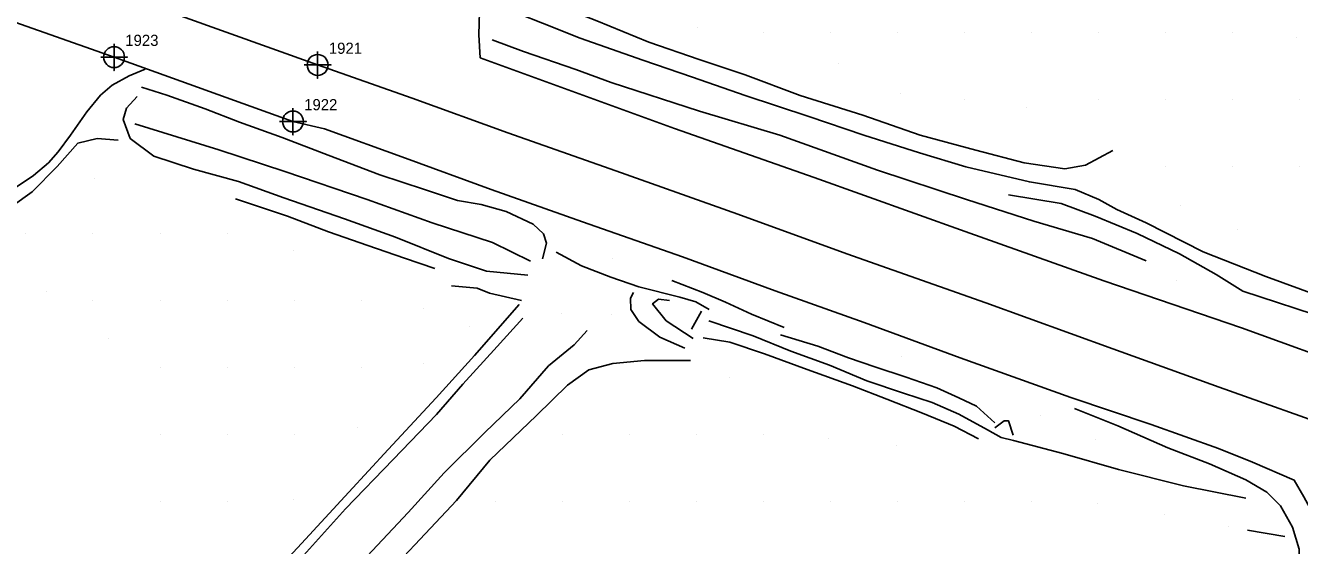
# Model space of a CAD drawing. Extents: x 1497074 to 1501343, y 481943 to 486114.
# Drawn here: x 1500304.3 to 1500589.4, y 482477.4 to 482593.8 of the extents above; entities that cross this region are included whole.
import ezdxf

# ---------------------------------------------------------------- set-up
doc = ezdxf.new("R2010")
doc.units = 0
for name, color, linetype in [('Exist DTM Crownline', 7, 'Continuous'), ('Exist DTM Crownline Cogo Number', 7, 'Continuous'), ('Exist DTM Crownline Cogo Point CELL', 7, 'Continuous'), ('Exist Roads EOP', 7, 'Continuous'), ('Exist Roads EOP Cogo Number', 7, 'Continuous'), ('Exist Roads EOP Cogo Point CELL', 7, 'Continuous'), ('PH Exist DTM Breakline', 7, 'Continuous'), ('PH Exist DTM Point', 7, 'Continuous')]:
    doc.layers.add(name, color=color, linetype=linetype)

msp = doc.modelspace()

# ---------------------------------------------------------------- linework, layer by layer
at = {"layer": 'Exist DTM Crownline'}
msp.add_lwpolyline([(1499395.36, 482985.02), (1499443.87, 482960.81), (1499493.08, 482936.36), (1499540.5, 482912.88), (1499586.46, 482890.36), (1499633.9, 482867.41), (1499680.88, 482845.25), (1499726.12, 482824.18), (1499773.19, 482803.77), (1499819.04, 482785.34), (1499906.6, 482751.56), (1499930.69, 482742.84), (1499979.87, 482724.77), (1500026.26, 482708.17), (1500077.15, 482689.67), (1500127.52, 482671.55), (1500177.68, 482653.78), (1500231.5, 482634.52), (1500279.65, 482617.19), (1500328.73, 482599.71), (1500369.66, 482584.94)], dxfattribs=at)
at = {"layer": 'Exist DTM Crownline Cogo Point CELL'}
msp.add_lwpolyline([(1500369.66, 482587.94), (1500369.66, 482581.94), (1500369.66, 482584.94), (1500372.66, 482584.94), (1500366.66, 482584.94)], dxfattribs=at)
msp.add_circle((1500369.66, 482584.94), 2.34, dxfattribs=at)
at = {"layer": 'Exist Roads EOP'}
msp.add_lwpolyline([(1500364.14, 482572.3), (1500324.1, 482586.7), (1500274.47, 482604.24), (1500226.4, 482621.51), (1500172.89, 482640.65), (1500123.05, 482658.39), (1500072.51, 482676.64), (1500021.62, 482694.94), (1499975.28, 482711.55), (1499955.26, 482716.33), (1499949.38, 482714.38), (1499941.38, 482710.37), (1499928.12, 482699.94), (1499921.66, 482694.39), (1499904.23, 482677.62), (1499903.33, 482678.08), (1499900.77, 482675.86), (1499864.51, 482643.53), (1499854.11, 482635.15), (1499853.12, 482633.84), (1499832.56, 482616.27)], dxfattribs=at)
at = {"layer": 'Exist Roads EOP Cogo Point CELL'}
for points in [[(1500324.1, 482589.7), (1500324.1, 482583.7), (1500324.1, 482586.7), (1500327.1, 482586.7), (1500321.1, 482586.7)], [(1500364.14, 482575.3), (1500364.14, 482569.3), (1500364.14, 482572.3), (1500367.14, 482572.3), (1500361.14, 482572.3)]]:
    msp.add_lwpolyline(points, dxfattribs=at)
for centre in [(1500324.1, 482586.7), (1500364.14, 482572.3)]:
    msp.add_circle(centre, 2.34, dxfattribs=at)
at = {"layer": 'PH Exist DTM Breakline'}
for points in [[(1500547.62, 482565.77), (1500541.54, 482562.52), (1500536.9, 482561.72), (1500527.81, 482563.03), (1500516.97, 482565.85), (1500504.53, 482569.25), (1500491.66, 482573.73), (1500477.65, 482578.13), (1500465.31, 482582.73), (1500455.04, 482586.17), (1500443.76, 482590.06), (1500432.14, 482594.82), (1500421.54, 482598.92), (1500418.01, 482600.86), (1500417.69, 482602.83), (1500418.26, 482607.14), (1500421.14, 482612.28)], [(1500405.93, 482599.51), (1500405.73, 482591.71), (1500406.05, 482586.53)], [(1500597.39, 482531.89), (1500581.86, 482537.56), (1500567.86, 482543.08), (1500555.09, 482549.62), (1500548.51, 482552.62), (1500544.53, 482554.85), (1500539.24, 482557.03), (1500528.98, 482558.76), (1500514.76, 482562.16), (1500504.39, 482565.28), (1500491.91, 482569.24), (1500479.6, 482573.43), (1500465.31, 482578.1), (1500453.59, 482582.18), (1500442.47, 482586), (1500428.38, 482590.96), (1500419.95, 482594.33), (1500414.71, 482596.39), (1500410.57, 482596.92)], [(1500408.71, 482590.6), (1500415.76, 482587.94), (1500427.44, 482583.92), (1500435.32, 482580.99), (1500455.09, 482574.64), (1500473.11, 482569.22), (1500494.93, 482561.37), (1500514.86, 482554.8), (1500529.97, 482549.97), (1500543.06, 482546.06), (1500555.08, 482541.13)], [(1500406.05, 482586.53), (1500449.56, 482570.71), (1500480.79, 482559.72), (1500514.61, 482547.63), (1500545.65, 482536.59), (1500576.45, 482526.09), (1500603.2, 482516.43), (1500637.04, 482504.51), (1500670.84, 482492.41), (1500696.34, 482483.22)], [(1500331.04, 482584.04), (1500327.45, 482582.49), (1500323.67, 482580.42), (1500321.08, 482578.16), (1500317.97, 482574.44), (1500314.37, 482569.2), (1500311.58, 482565.5), (1500309.42, 482563.01), (1500306.06, 482560.22), (1500301.06, 482556.84)], [(1500369.66, 482584.94), (1500390.85, 482577.55), (1500412.23, 482569.72), (1500436.39, 482561.28), (1500463.73, 482551.56), (1500488.07, 482542.65), (1500519.2, 482531.68), (1500547.67, 482521.38), (1500571.4, 482512.81), (1500599.53, 482502.81), (1500623.37, 482494.22), (1500646.19, 482486.12), (1500679.44, 482473.93), (1500690.61, 482470.06)], [(1500416.68, 482537.86), (1500407.48, 482538.76), (1500398.98, 482541.63), (1500387.05, 482546.43), (1500375.66, 482550.5), (1500362.06, 482555.21), (1500351.97, 482558.88), (1500341.9, 482561.63), (1500333, 482564.53), (1500327.73, 482568.49), (1500326.14, 482572.74), (1500326.9, 482575.27), (1500329.27, 482577.92)], [(1500419.97, 482541.55), (1500420.88, 482545.08), (1500420.24, 482547.17), (1500417.93, 482549.28), (1500411.85, 482552.16), (1500406.26, 482553.73), (1500400.97, 482554.57), (1500393.58, 482557.04), (1500383.58, 482560.33), (1500371.98, 482564.73), (1500361.75, 482568.72), (1500352.2, 482572.12), (1500344.45, 482575.09), (1500335.89, 482578.2), (1500330.24, 482579.97)], [(1500595.23, 482475.62), (1500594.21, 482480.19), (1500592.65, 482484.14), (1500590.39, 482488.29), (1500588.26, 482492.01), (1500578.87, 482496.04), (1500571.31, 482499.06), (1500556.23, 482504.45), (1500538.22, 482510.5), (1500513.46, 482519.4), (1500491.97, 482527.27), (1500472.06, 482534.37), (1500451.31, 482541.98), (1500428.93, 482549.82), (1500408.49, 482557.07), (1500389.35, 482564.11), (1500371.23, 482570.64), (1500364.14, 482572.3)], [(1500328.74, 482571.74), (1500347.55, 482565.97), (1500362.35, 482561.08), (1500380.71, 482554.84), (1500395.32, 482549.61), (1500408.78, 482545.19), (1500417.33, 482541.02)], [(1500316.01, 482567.47), (1500311.38, 482562.21), (1500305.73, 482556.56), (1500296.77, 482550.15), (1500289.24, 482543.46), (1500284.31, 482538.79)], [(1500325.02, 482568.13), (1500320.33, 482568.49), (1500316.01, 482567.47)], [(1500698.83, 482489.93), (1500673.29, 482499.49), (1500655.4, 482505.71), (1500637.76, 482512.19), (1500619.48, 482519.28), (1500596.32, 482527.89), (1500576.71, 482534.3), (1500570.75, 482538.05), (1500562.55, 482542.64), (1500553.11, 482547.19), (1500543.66, 482551.1), (1500536.09, 482553.92), (1500524.31, 482555.86)], [(1500395.91, 482539.41), (1500389.12, 482541.67), (1500380.92, 482544.56), (1500372.07, 482547.59), (1500362.95, 482551.13), (1500351.31, 482555.01)], [(1500441.57, 482535.3), (1500435.28, 482537.46), (1500428.75, 482539.95), (1500423.02, 482543.06)], [(1500415.3, 482532.19), (1500408.13, 482533.89), (1500405.36, 482534.98), (1500399.62, 482535.5)], [(1500441.57, 482535.3), (1500450.76, 482532.97), (1500454.29, 482531.88), (1500457.27, 482530.2)], [(1500474.07, 482526.14), (1500466.76, 482529.18), (1500460.94, 482531.86), (1500455.85, 482534.02), (1500448.94, 482536.7)], [(1500451.87, 482521.55), (1500446.24, 482524.01), (1500441.56, 482527.5), (1500439.74, 482530.17), (1500439.67, 482532.72), (1500440.39, 482534.02)], [(1500453.74, 482523.7), (1500447.68, 482527.7), (1500444.64, 482531.49), (1500445.97, 482532.54), (1500448.39, 482532.21)], [(1500414.77, 482531.35), (1500404.74, 482519.88), (1500396.19, 482510.44), (1500385.47, 482498.82), (1500376.62, 482489.29), (1500366.04, 482477.81), (1500357.64, 482468.72)], [(1500455.6, 482529.79), (1500453.34, 482525.76)], [(1500285.41, 482386.96), (1500299.03, 482401.49), (1500308.78, 482412.24), (1500317.75, 482421.43), (1500325.41, 482430.17), (1500335.98, 482441.88), (1500346.65, 482453.12), (1500355.52, 482462.68), (1500365.8, 482474.4), (1500375.87, 482485.58), (1500386.54, 482496.65), (1500396.23, 482506.66), (1500402.14, 482513.46), (1500409.83, 482521.94), (1500415.62, 482528.28)], [(1500577.38, 482487.98), (1500563.48, 482490.72), (1500548.89, 482494.36), (1500536.41, 482497.95), (1500525.39, 482500.85), (1500522.66, 482501.54), (1500519.56, 482503.28), (1500513.14, 482506.78), (1500507.23, 482509.36), (1500500.78, 482511.49), (1500492.55, 482514.26), (1500484.2, 482517.75), (1500475.56, 482520.9), (1500467.12, 482524.34), (1500457.24, 482527.67)], [(1500233.26, 482310.35), (1500245.7, 482324.29), (1500256.9, 482336.95), (1500267.74, 482349.8), (1500279.3, 482362.4), (1500288.96, 482372.62), (1500298.86, 482383.6), (1500308.27, 482393.74), (1500317.46, 482404.17), (1500326.98, 482415.11), (1500337.44, 482427.39), (1500348.01, 482438.92), (1500359.2, 482450.76), (1500370.53, 482463.21), (1500380.71, 482474.98), (1500389.92, 482484.73), (1500398, 482493.6), (1500407.07, 482502.7), (1500414.94, 482510.19), (1500421.33, 482517.62), (1500427.09, 482522.27), (1500430.02, 482525.51)], [(1500455.98, 482523.82), (1500461.95, 482522.92), (1500469.65, 482520.3), (1500479.23, 482516.74), (1500489.37, 482513.09), (1500497.03, 482510.14), (1500505.05, 482506.96), (1500512.13, 482504.08), (1500517.59, 482501.23)], [(1500521.22, 482504.86), (1500517.12, 482508.58), (1500513.16, 482510.42), (1500508.28, 482512.7), (1500501.38, 482515.03), (1500494.36, 482517.34), (1500488.45, 482519.38), (1500481.62, 482521.98), (1500473.28, 482524.5)], [(1500453.11, 482518.77), (1500442.8, 482518.79), (1500435.75, 482518.13), (1500430.37, 482516.69), (1500425.59, 482513.25), (1500418.63, 482506.48), (1500408.2, 482496.45), (1500400.76, 482487.43), (1500391.45, 482477.55), (1500383.79, 482469.46)], [(1500588.26, 482467.46), (1500589.39, 482472.03), (1500589.35, 482476.53), (1500587.85, 482481.48), (1500585.16, 482486.27), (1500582.07, 482489.31), (1500577.42, 482492.09), (1500569.24, 482495.63), (1500559.98, 482499.25), (1500548.78, 482504.19), (1500539.04, 482508.06)], [(1500525.34, 482502.04), (1500524.26, 482505.31), (1500523.3, 482505.31), (1500521.25, 482503.73)], [(1500586.12, 482479.36), (1500577.76, 482480.78)]]:
    msp.add_lwpolyline(points, dxfattribs=at)
at = {"layer": 'PH Exist DTM Point'}
for p, q in [((1500454.75, 482593.35), (1500454.75, 482593.35)), ((1500469.46, 482592.21), (1500469.46, 482592.21)), ((1500484.38, 482592.25), (1500484.38, 482592.25)), ((1500499.38, 482592.25), (1500499.38, 482592.25)), ((1500514.38, 482592.25), (1500514.38, 482592.25)), ((1500529.38, 482592.25), (1500529.38, 482592.25)), ((1500544.38, 482592.25), (1500544.38, 482592.25)), ((1500559.38, 482592.25), (1500559.38, 482592.25)), ((1500574.38, 482592.25), (1500574.38, 482592.25)), ((1500588.78, 482591.17), (1500588.78, 482591.17)), ((1500486.25, 482585.32), (1500486.25, 482585.32)), ((1500500.15, 482578.65), (1500500.15, 482578.65)), ((1500514.39, 482577.27), (1500514.39, 482577.27)), ((1500528.42, 482575.53), (1500528.42, 482575.53)), ((1500544.38, 482577.25), (1500544.38, 482577.25)), ((1500559.38, 482577.25), (1500559.38, 482577.25)), ((1500574.38, 482577.25), (1500574.38, 482577.25)), ((1500589.38, 482577.25), (1500589.38, 482577.25)), ((1500559.38, 482562.25), (1500559.38, 482562.25)), ((1500574.38, 482562.25), (1500574.38, 482562.25)), ((1500589.38, 482562.25), (1500589.38, 482562.25)), ((1500319.78, 482559.63), (1500319.78, 482559.63)), ((1500562.82, 482553.39), (1500562.82, 482553.39)), ((1500304.38, 482547.25), (1500304.38, 482547.25)), ((1500319.38, 482547.25), (1500319.38, 482547.25)), ((1500334.38, 482547.25), (1500334.38, 482547.25)), ((1500349.38, 482547.25), (1500349.38, 482547.25)), ((1500575.57, 482548.14), (1500575.57, 482548.14)), ((1500364.29, 482543.43), (1500364.29, 482543.43)), ((1500435.62, 482541.62), (1500435.62, 482541.62)), ((1500561.91, 482536.77), (1500561.91, 482536.77)), ((1500309.01, 482534.23), (1500309.01, 482534.23)), ((1500319.38, 482532.25), (1500319.38, 482532.25)), ((1500334.38, 482532.25), (1500334.38, 482532.25)), ((1500349.38, 482532.25), (1500349.38, 482532.25)), ((1500364.38, 482532.25), (1500364.38, 482532.25)), ((1500379.38, 482532.25), (1500379.38, 482532.25)), ((1500393.42, 482530.53), (1500393.42, 482530.53)), ((1500424.18, 482529.33), (1500424.18, 482529.33)), ((1500435.43, 482528.97), (1500435.43, 482528.97)), ((1500322.9, 482523.69), (1500322.9, 482523.69)), ((1500403.74, 482526.35), (1500403.74, 482526.35)), ((1500393.37, 482518.01), (1500393.37, 482518.01)), ((1500500.28, 482519.6), (1500500.28, 482519.6)), ((1500334.38, 482517.25), (1500334.38, 482517.25)), ((1500349.38, 482517.25), (1500349.38, 482517.25)), ((1500364.38, 482517.25), (1500364.38, 482517.25)), ((1500379.38, 482517.25), (1500379.38, 482517.25)), ((1500461.92, 482515.08), (1500461.92, 482515.08)), ((1500378.68, 482503.74), (1500378.68, 482503.74)), ((1500531.55, 482506.5), (1500531.55, 482506.5)), ((1500334.38, 482502.25), (1500334.38, 482502.25)), ((1500349.38, 482502.25), (1500349.38, 482502.25)), ((1500364.38, 482502.25), (1500364.38, 482502.25)), ((1500424.38, 482502.25), (1500424.38, 482502.25)), ((1500439.38, 482502.25), (1500439.38, 482502.25)), ((1500454.38, 482502.25), (1500454.38, 482502.25)), ((1500469.38, 482502.25), (1500469.38, 482502.25)), ((1500484.1, 482501.24), (1500484.1, 482501.24)), ((1500543.73, 482501.05), (1500543.73, 482501.05)), ((1500499.33, 482499.65), (1500499.33, 482499.65)), ((1500334.38, 482487.25), (1500334.38, 482487.25)), ((1500349.38, 482487.25), (1500349.38, 482487.25)), ((1500364.35, 482487.64), (1500364.35, 482487.64)), ((1500409.38, 482487.25), (1500409.38, 482487.25)), ((1500424.38, 482487.25), (1500424.38, 482487.25)), ((1500439.38, 482487.25), (1500439.38, 482487.25)), ((1500454.38, 482487.25), (1500454.38, 482487.25)), ((1500469.38, 482487.25), (1500469.38, 482487.25)), ((1500484.38, 482487.25), (1500484.38, 482487.25)), ((1500499.38, 482487.25), (1500499.38, 482487.25)), ((1500514.38, 482487.25), (1500514.38, 482487.25)), ((1500529.38, 482487.25), (1500529.38, 482487.25)), ((1500544.13, 482486.8), (1500544.13, 482486.8)), ((1500559.12, 482484.37), (1500559.12, 482484.37)), ((1500573.42, 482481.53), (1500573.42, 482481.53))]:
    msp.add_line(p, q, dxfattribs=at)

# ---------------------------------------------------------------- texts
at = {"layer": 'Exist DTM Crownline Cogo Number'}
msp.add_text('1921', height=2.5, dxfattribs=at).set_placement((1500372.16, 482587.44))
at = {"layer": 'Exist Roads EOP Cogo Number'}
for s, p in [('1923', (1500326.6, 482589.21)), ('1922', (1500366.64, 482574.81))]:
    msp.add_text(s, height=2.5, dxfattribs=at).set_placement(p)

doc.saveas('drawing.dxf')
